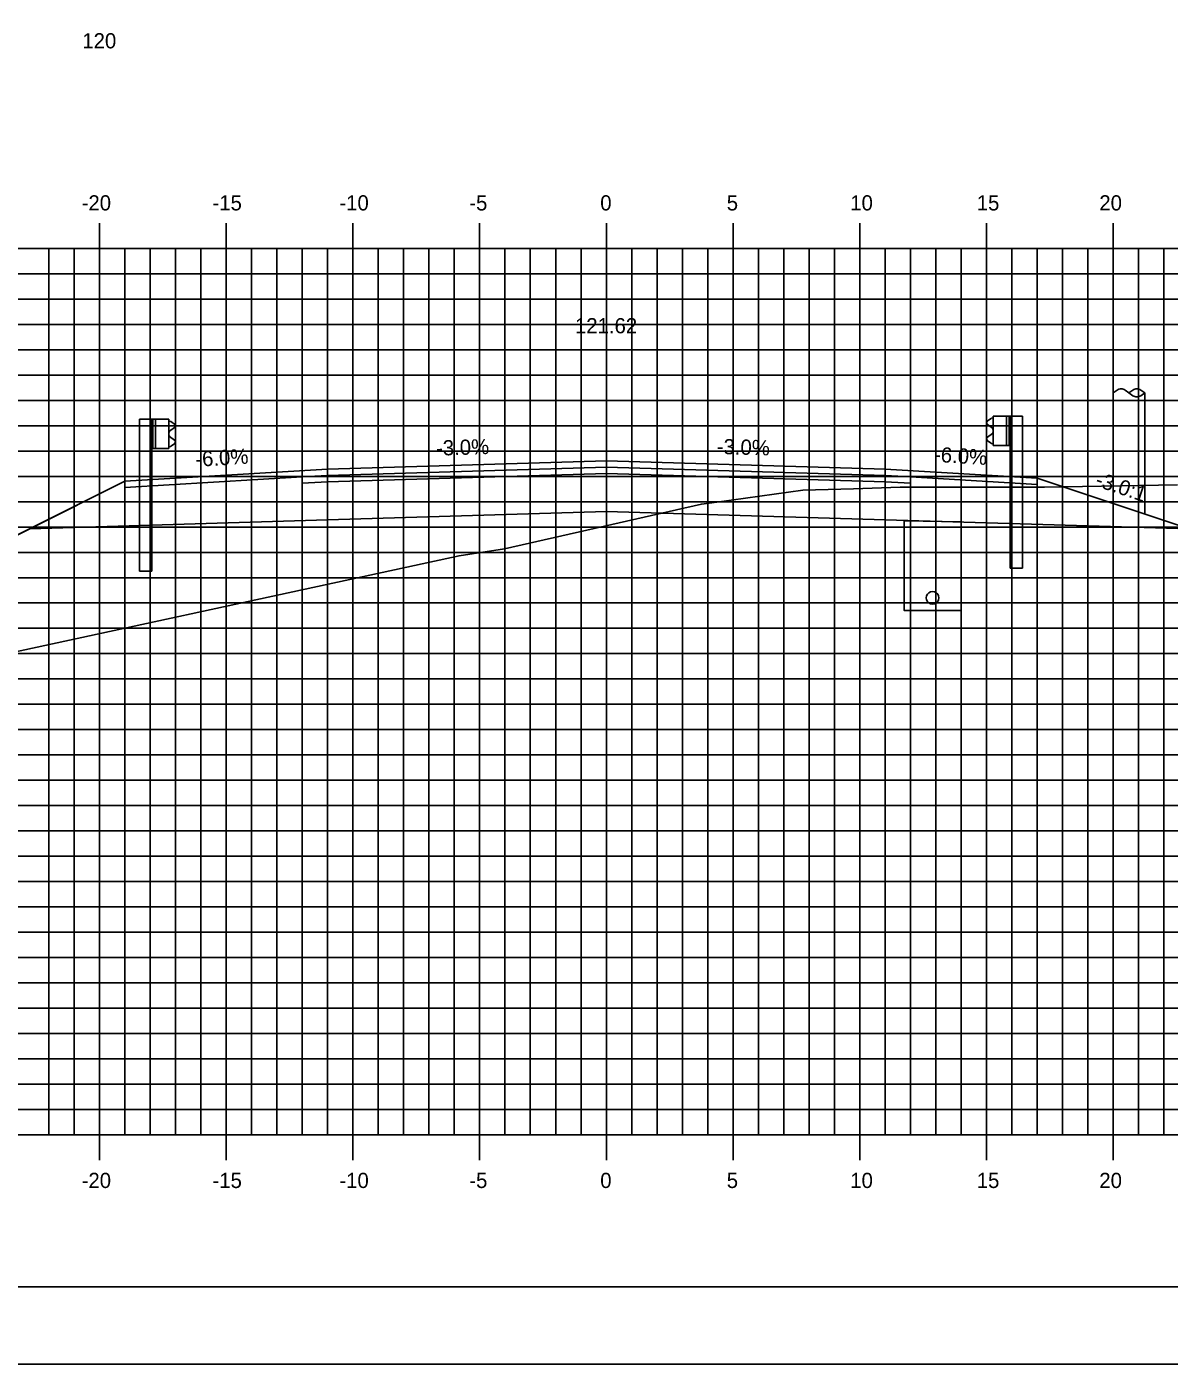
# Model space of a CAD drawing. Extents: x 850598 to 870284, y 366541 to 366651.
# Drawn here: x 858389.5 to 858434.6, y 366541.2 to 366594 of the extents above; entities that cross this region are included whole.
import ezdxf

# ---------------------------------------------------------------- set-up
doc = ezdxf.new("R2010")
doc.units = 0
for name, color, linetype in [('ANNOTATION', 7, 'Continuous'), ('BORDER', 7, 'Continuous'), ('D_Drainage_Underdrain', 7, 'Continuous'), ('D_Drainage_Underdrain_06in', 7, 'Continuous'), ('D_Guardrail_Beam_Lt', 7, 'Continuous'), ('D_Guardrail_Beam_Rt', 7, 'Continuous'), ('D_Roadway_Centerline', 7, 'Continuous'), ('D_Roadway_Centerline_Text', 7, 'Continuous'), ('D_Roadway_Edge_Shoulder', 7, 'Continuous'), ('D_Roadway_Edge_TW', 7, 'Continuous'), ('D_Roadway_Pavement', 7, 'Continuous'), ('D_Roadway_SlopeLines', 7, 'Continuous'), ('D_Roadway_SubGrade', 7, 'Continuous'), ('D_Utilities_Pole_Joint', 7, 'Continuous'), ('H_V ANNOTATION', 7, 'Continuous'), ('MAJOR', 7, 'Continuous'), ('MINOR', 7, 'Continuous'), ('PLOT BOUNDARY', 7, 'Continuous'), ('S_Roadway_Centerline', 7, 'Continuous')]:
    doc.layers.add(name, color=color, linetype=linetype)

msp = doc.modelspace()

# ---------------------------------------------------------------- linework, layer by layer
at = {"layer": 'BORDER'}
msp.add_line((858367.376, 366544.225), (858527.376, 366544.225), dxfattribs=at)
at = {"layer": 'D_Drainage_Underdrain'}
msp.add_lwpolyline([(858426.376, 366574.43), (858426.376, 366570.93), (858424.126, 366570.93), (858424.126, 366574.475)], close=True, dxfattribs=at)
at = {"layer": 'D_Drainage_Underdrain_06in'}
msp.add_lwpolyline([(858425.251, 366571.68), (858425.174, 366571.668), (858425.104, 366571.632), (858425.049, 366571.577), (858425.013, 366571.507), (858425.001, 366571.43), (858425.013, 366571.353), (858425.049, 366571.283), (858425.104, 366571.228), (858425.174, 366571.192), (858425.251, 366571.18), (858425.328, 366571.192), (858425.398, 366571.228), (858425.453, 366571.283), (858425.489, 366571.353), (858425.501, 366571.43), (858425.489, 366571.507), (858425.453, 366571.577), (858425.398, 366571.632), (858425.328, 366571.668)], close=True, dxfattribs=at)
at = {"layer": 'D_Guardrail_Beam_Lt'}
for p, q in [((858393.947, 366578.486), (858393.947, 366572.486)), ((858394.418, 366578.486), (858393.947, 366578.486)), ((858395.105, 366578.486), (858394.418, 366578.486)), ((858394.418, 366578.486), (858394.418, 366577.319)), ((858394.48, 366578.486), (858394.48, 366577.319)), ((858394.584, 366578.486), (858394.584, 366577.319)), ((858395.105, 366577.319), (858395.105, 366578.486)), ((858395.105, 366578.411), (858395.178, 366578.398)), ((858395.195, 366578.392), (858395.339, 366578.292)), ((858395.11, 366577.948), (858395.11, 366577.857)), ((858395.339, 366578.149), (858395.143, 366578.012)), ((858395.143, 366577.793), (858395.339, 366577.656)), ((858394.418, 366577.319), (858395.105, 366577.319)), ((858394.439, 366572.486), (858394.439, 366577.319)), ((858395.178, 366577.406), (858395.105, 366577.394)), ((858395.339, 366577.513), (858395.195, 366577.413)), ((858394.439, 366572.486), (858393.947, 366572.486))]:
    msp.add_line(p, q, dxfattribs=at)
for centre, major_axis, start_param, end_param in [((858395.171, 366578.358), (0.0417, 0), 0.959931, 1.396263), ((858395.288, 366578.22), (0.0877, 0), 5.323254, 7.243116), ((858395.189, 366577.948), (-0.0789, 0), 5.323254, 6.283185), ((858395.189, 366577.857), (-0.0789, 0), 6.283185, 7.243116), ((858395.288, 366577.585), (0.0877, 0), 5.323254, 7.243116), ((858395.171, 366577.447), (0.0417, 0), 4.886922, 5.323254)]:
    msp.add_ellipse(centre, major_axis=major_axis, ratio=0.995501, start_param=start_param, end_param=end_param, dxfattribs=at)
at = {"layer": 'D_Guardrail_Beam_Rt'}
for p, q in [((858427.557, 366578.512), (858427.413, 366578.412)), ((858427.413, 366578.269), (858427.609, 366578.132)), ((858427.647, 366578.531), (858427.574, 366578.518)), ((858427.647, 366578.606), (858428.334, 366578.606)), ((858427.647, 366577.439), (858427.647, 366578.606)), ((858428.168, 366578.606), (858428.168, 366577.439)), ((858428.272, 366578.606), (858428.272, 366577.439)), ((858428.334, 366578.606), (858428.805, 366578.606)), ((858428.334, 366578.606), (858428.334, 366577.439)), ((858428.805, 366578.606), (858428.805, 366572.606)), ((858427.609, 366577.913), (858427.413, 366577.776)), ((858427.642, 366578.068), (858427.642, 366577.977)), ((858427.413, 366577.633), (858427.557, 366577.533)), ((858427.574, 366577.526), (858427.647, 366577.514)), ((858428.334, 366577.439), (858427.647, 366577.439)), ((858428.314, 366572.606), (858428.314, 366577.439)), ((858428.314, 366572.606), (858428.805, 366572.606))]:
    msp.add_line(p, q, dxfattribs=at)
for centre, major_axis, start_param, end_param in [((858427.464, 366578.34), (-0.0877, 0), 5.323254, 7.243116), ((858427.581, 366578.478), (-0.0417, 0), 4.886922, 5.323254), ((858427.464, 366577.705), (-0.0877, 0), 5.323254, 7.243116), ((858427.564, 366578.068), (0.0789, 0), 0, 0.959931), ((858427.564, 366577.977), (0.0789, 0), 5.323254, 6.283185), ((858427.581, 366577.567), (-0.0417, 0), 0.959931, 1.396263)]:
    msp.add_ellipse(centre, major_axis=major_axis, ratio=0.995501, start_param=start_param, end_param=end_param, dxfattribs=at)
at = {"layer": 'D_Roadway_Centerline'}
msp.add_lwpolyline([(858372.376, 366565.532), (858383.376, 366571.032), (858389.631, 366574.16), (858393.376, 366576.032), (858395.376, 366576.152), (858401.376, 366576.512), (858412.376, 366576.842), (858423.376, 366576.512), (858427.376, 366576.272), (858429.376, 366576.152), (858435.376, 366574.152), (858495.021, 366563.225), (858512.376, 366560.046)], dxfattribs=at)
at = {"layer": 'D_Roadway_Edge_Shoulder'}
for points in [[(858401.376, 366576.512), (858395.376, 366576.152), (858395.376, 366576.152), (858393.376, 366576.032), (858393.376, 366575.782), (858400.376, 366576.202), (858401.376, 366576.262)], [(858423.376, 366576.512), (858427.376, 366576.272), (858427.376, 366576.272), (858429.376, 366576.152), (858429.376, 366575.902), (858424.376, 366576.202), (858423.376, 366576.262)]]:
    msp.add_lwpolyline(points, close=True, dxfattribs=at)
at = {"layer": 'D_Roadway_Edge_TW'}
msp.add_lwpolyline([(858401.376, 366576.262), (858401.376, 366576.512), (858412.376, 366576.842), (858423.376, 366576.512), (858423.376, 366576.262), (858412.376, 366576.592)], close=True, dxfattribs=at)
at = {"layer": 'D_Roadway_Pavement'}
for points in [[(858401.376, 366576.012), (858401.376, 366576.262), (858412.376, 366576.592), (858423.376, 366576.262), (858423.376, 366576.012), (858412.376, 366576.342)], [(858401.376, 366576.262), (858400.376, 366576.202), (858400.376, 366575.952), (858401.376, 366576.012)], [(858423.376, 366576.262), (858424.376, 366576.202), (858424.376, 366575.952), (858423.376, 366576.012)]]:
    msp.add_lwpolyline(points, close=True, dxfattribs=at)
at = {"layer": 'D_Roadway_SlopeLines'}
msp.add_lwpolyline([(858393.376, 366576.032), (858383.376, 366571.032)], dxfattribs=at)
at = {"layer": 'D_Roadway_SubGrade'}
for points in [[(858401.376, 366576.012), (858400.376, 366575.952), (858400.376, 366576.202), (858393.376, 366575.782), (858393.376, 366576.032), (858389.631, 366574.16), (858401.376, 366574.512)], [(858401.376, 366574.512), (858401.376, 366576.012), (858412.376, 366576.342), (858423.376, 366576.012), (858423.376, 366574.512), (858412.376, 366574.842)], [(858423.376, 366576.012), (858424.376, 366575.952), (858424.376, 366576.202), (858429.376, 366575.902), (858429.376, 366576.152), (858435.376, 366574.152), (858423.376, 366574.512)]]:
    msp.add_lwpolyline(points, close=True, dxfattribs=at)
msp.add_lwpolyline([(858393.376, 366576.032), (858389.631, 366574.16), (858393.376, 366576.032)], dxfattribs=at)
at = {"layer": 'D_Utilities_Pole_Joint'}
for p, q in [((858432.376, 366579.522), (858432.532, 366579.632)), ((858432.376, 366574.764), (858432.376, 366579.522)), ((858432.845, 366579.632), (858433.001, 366579.522)), ((858433.157, 366579.632), (858433.001, 366579.522)), ((858433.001, 366579.522), (858433.157, 366579.411)), ((858433.626, 366579.522), (858433.47, 366579.632)), ((858433.47, 366579.411), (858433.626, 366579.522)), ((858433.626, 366574.764), (858433.626, 366579.522))]:
    msp.add_line(p, q, dxfattribs=at)
for centre, start, end in [((858432.688, 366579.412), 90, 125.2644), ((858432.688, 366579.412), 54.7356, 90), ((858433.313, 366579.412), 90, 125.2644), ((858433.313, 366579.633), 234.7356, 270), ((858433.313, 366579.412), 54.7356, 90), ((858433.313, 366579.633), 270, 305.2644)]:
    msp.add_arc(centre, 0.271, start, end, dxfattribs=at)
at = {"layer": 'MAJOR'}
for p, q in [((858392.376, 366586.227), (858392.376, 366585.225)), ((858392.376, 366586.227), (858392.376, 366585.225)), ((858397.376, 366586.227), (858397.376, 366585.225)), ((858397.376, 366586.227), (858397.376, 366585.225)), ((858402.376, 366586.227), (858402.376, 366585.225)), ((858402.376, 366586.227), (858402.376, 366585.225)), ((858407.376, 366586.227), (858407.376, 366585.225)), ((858407.376, 366586.227), (858407.376, 366585.225)), ((858412.376, 366586.227), (858412.376, 366585.225)), ((858412.376, 366586.227), (858412.376, 366585.225)), ((858417.376, 366586.227), (858417.376, 366585.225)), ((858417.376, 366586.227), (858417.376, 366585.225)), ((858422.376, 366586.227), (858422.376, 366585.225)), ((858422.376, 366586.227), (858422.376, 366585.225)), ((858427.376, 366586.227), (858427.376, 366585.225)), ((858427.376, 366586.227), (858427.376, 366585.225)), ((858432.376, 366586.227), (858432.376, 366585.225)), ((858432.376, 366586.227), (858432.376, 366585.225)), ((858372.376, 366585.225), (858512.376, 366585.225)), ((858372.376, 366585.225), (858512.376, 366585.225)), ((858372.376, 366585.225), (858512.376, 366585.225)), ((858372.376, 366585.225), (858512.376, 366585.225)), ((858392.376, 366550.225), (858392.376, 366585.225)), ((858392.376, 366550.225), (858392.376, 366585.225)), ((858397.376, 366550.225), (858397.376, 366585.225)), ((858397.376, 366550.225), (858397.376, 366585.225)), ((858402.376, 366550.225), (858402.376, 366585.225)), ((858402.376, 366550.225), (858402.376, 366585.225)), ((858407.376, 366550.225), (858407.376, 366585.225)), ((858407.376, 366550.225), (858407.376, 366585.225)), ((858412.376, 366550.225), (858412.376, 366585.225)), ((858412.376, 366550.225), (858412.376, 366585.225)), ((858417.376, 366550.225), (858417.376, 366585.225)), ((858417.376, 366550.225), (858417.376, 366585.225)), ((858422.376, 366550.225), (858422.376, 366585.225)), ((858422.376, 366550.225), (858422.376, 366585.225)), ((858427.376, 366550.225), (858427.376, 366585.225)), ((858427.376, 366550.225), (858427.376, 366585.225)), ((858432.376, 366550.225), (858432.376, 366585.225)), ((858432.376, 366550.225), (858432.376, 366585.225)), ((858372.376, 366580.225), (858512.376, 366580.225)), ((858372.376, 366580.225), (858512.376, 366580.225)), ((858372.376, 366575.225), (858512.376, 366575.225)), ((858372.376, 366575.225), (858512.376, 366575.225)), ((858372.376, 366570.225), (858512.376, 366570.225)), ((858372.376, 366570.225), (858512.376, 366570.225)), ((858372.376, 366565.225), (858512.376, 366565.225)), ((858372.376, 366565.225), (858512.376, 366565.225)), ((858372.376, 366560.225), (858512.376, 366560.225)), ((858372.376, 366560.225), (858512.376, 366560.225)), ((858372.376, 366555.225), (858512.376, 366555.225)), ((858372.376, 366555.225), (858512.376, 366555.225)), ((858372.376, 366550.225), (858512.376, 366550.225)), ((858372.376, 366550.225), (858512.376, 366550.225)), ((858372.376, 366550.225), (858512.376, 366550.225)), ((858372.376, 366550.225), (858512.376, 366550.225)), ((858392.376, 366549.223), (858392.376, 366550.225)), ((858392.376, 366549.223), (858392.376, 366550.225)), ((858397.376, 366549.223), (858397.376, 366550.225)), ((858397.376, 366549.223), (858397.376, 366550.225)), ((858402.376, 366549.223), (858402.376, 366550.225)), ((858402.376, 366549.223), (858402.376, 366550.225)), ((858407.376, 366549.223), (858407.376, 366550.225)), ((858407.376, 366549.223), (858407.376, 366550.225)), ((858412.376, 366549.223), (858412.376, 366550.225)), ((858412.376, 366549.223), (858412.376, 366550.225)), ((858417.376, 366549.223), (858417.376, 366550.225)), ((858417.376, 366549.223), (858417.376, 366550.225)), ((858422.376, 366549.223), (858422.376, 366550.225)), ((858422.376, 366549.223), (858422.376, 366550.225)), ((858427.376, 366549.223), (858427.376, 366550.225)), ((858427.376, 366549.223), (858427.376, 366550.225)), ((858432.376, 366549.223), (858432.376, 366550.225)), ((858432.376, 366549.223), (858432.376, 366550.225))]:
    msp.add_line(p, q, dxfattribs=at)
at = {"layer": 'MINOR'}
for p, q in [((858390.376, 366550.225), (858390.376, 366585.225)), ((858390.376, 366550.225), (858390.376, 366585.225)), ((858391.376, 366550.225), (858391.376, 366585.225)), ((858391.376, 366550.225), (858391.376, 366585.225)), ((858393.376, 366550.225), (858393.376, 366585.225)), ((858393.376, 366550.225), (858393.376, 366585.225)), ((858394.376, 366550.225), (858394.376, 366585.225)), ((858394.376, 366550.225), (858394.376, 366585.225)), ((858395.376, 366550.225), (858395.376, 366585.225)), ((858395.376, 366550.225), (858395.376, 366585.225)), ((858396.376, 366550.225), (858396.376, 366585.225)), ((858396.376, 366550.225), (858396.376, 366585.225)), ((858398.376, 366550.225), (858398.376, 366585.225)), ((858398.376, 366550.225), (858398.376, 366585.225)), ((858399.376, 366550.225), (858399.376, 366585.225)), ((858399.376, 366550.225), (858399.376, 366585.225)), ((858400.376, 366550.225), (858400.376, 366585.225)), ((858400.376, 366550.225), (858400.376, 366585.225)), ((858401.376, 366550.225), (858401.376, 366585.225)), ((858401.376, 366550.225), (858401.376, 366585.225)), ((858403.376, 366550.225), (858403.376, 366585.225)), ((858403.376, 366550.225), (858403.376, 366585.225)), ((858404.376, 366550.225), (858404.376, 366585.225)), ((858404.376, 366550.225), (858404.376, 366585.225)), ((858405.376, 366550.225), (858405.376, 366585.225)), ((858405.376, 366550.225), (858405.376, 366585.225)), ((858406.376, 366550.225), (858406.376, 366585.225)), ((858406.376, 366550.225), (858406.376, 366585.225)), ((858408.376, 366550.225), (858408.376, 366585.225)), ((858408.376, 366550.225), (858408.376, 366585.225)), ((858409.376, 366550.225), (858409.376, 366585.225)), ((858409.376, 366550.225), (858409.376, 366585.225)), ((858410.376, 366550.225), (858410.376, 366585.225)), ((858410.376, 366550.225), (858410.376, 366585.225)), ((858411.376, 366550.225), (858411.376, 366585.225)), ((858411.376, 366550.225), (858411.376, 366585.225)), ((858413.376, 366550.225), (858413.376, 366585.225)), ((858413.376, 366550.225), (858413.376, 366585.225)), ((858414.376, 366550.225), (858414.376, 366585.225)), ((858414.376, 366550.225), (858414.376, 366585.225)), ((858415.376, 366550.225), (858415.376, 366585.225)), ((858415.376, 366550.225), (858415.376, 366585.225)), ((858416.376, 366550.225), (858416.376, 366585.225)), ((858416.376, 366550.225), (858416.376, 366585.225)), ((858418.376, 366550.225), (858418.376, 366585.225)), ((858418.376, 366550.225), (858418.376, 366585.225)), ((858419.376, 366550.225), (858419.376, 366585.225)), ((858419.376, 366550.225), (858419.376, 366585.225)), ((858420.376, 366550.225), (858420.376, 366585.225)), ((858420.376, 366550.225), (858420.376, 366585.225)), ((858421.376, 366550.225), (858421.376, 366585.225)), ((858421.376, 366550.225), (858421.376, 366585.225)), ((858423.376, 366550.225), (858423.376, 366585.225)), ((858423.376, 366550.225), (858423.376, 366585.225)), ((858424.376, 366550.225), (858424.376, 366585.225)), ((858424.376, 366550.225), (858424.376, 366585.225)), ((858425.376, 366550.225), (858425.376, 366585.225)), ((858425.376, 366550.225), (858425.376, 366585.225)), ((858426.376, 366550.225), (858426.376, 366585.225)), ((858426.376, 366550.225), (858426.376, 366585.225)), ((858428.376, 366550.225), (858428.376, 366585.225)), ((858428.376, 366550.225), (858428.376, 366585.225)), ((858429.376, 366550.225), (858429.376, 366585.225)), ((858429.376, 366550.225), (858429.376, 366585.225)), ((858430.376, 366550.225), (858430.376, 366585.225)), ((858430.376, 366550.225), (858430.376, 366585.225)), ((858431.376, 366550.225), (858431.376, 366585.225)), ((858431.376, 366550.225), (858431.376, 366585.225)), ((858433.376, 366550.225), (858433.376, 366585.225)), ((858433.376, 366550.225), (858433.376, 366585.225)), ((858434.376, 366550.225), (858434.376, 366585.225)), ((858434.376, 366550.225), (858434.376, 366585.225)), ((858372.376, 366584.225), (858512.376, 366584.225)), ((858372.376, 366584.225), (858512.376, 366584.225)), ((858372.376, 366583.225), (858512.376, 366583.225)), ((858372.376, 366583.225), (858512.376, 366583.225)), ((858372.376, 366582.225), (858512.376, 366582.225)), ((858372.376, 366582.225), (858512.376, 366582.225)), ((858372.376, 366581.225), (858512.376, 366581.225)), ((858372.376, 366581.225), (858512.376, 366581.225)), ((858372.376, 366579.225), (858512.376, 366579.225)), ((858372.376, 366579.225), (858512.376, 366579.225)), ((858372.376, 366578.225), (858512.376, 366578.225)), ((858372.376, 366578.225), (858512.376, 366578.225)), ((858372.376, 366577.225), (858512.376, 366577.225)), ((858372.376, 366577.225), (858512.376, 366577.225)), ((858372.376, 366576.225), (858512.376, 366576.225)), ((858372.376, 366576.225), (858512.376, 366576.225)), ((858372.376, 366574.225), (858512.376, 366574.225)), ((858372.376, 366574.225), (858512.376, 366574.225)), ((858372.376, 366573.225), (858512.376, 366573.225)), ((858372.376, 366573.225), (858512.376, 366573.225)), ((858372.376, 366572.225), (858512.376, 366572.225)), ((858372.376, 366572.225), (858512.376, 366572.225)), ((858372.376, 366571.225), (858512.376, 366571.225)), ((858372.376, 366571.225), (858512.376, 366571.225)), ((858372.376, 366569.225), (858512.376, 366569.225)), ((858372.376, 366569.225), (858512.376, 366569.225)), ((858372.376, 366568.225), (858512.376, 366568.225)), ((858372.376, 366568.225), (858512.376, 366568.225)), ((858372.376, 366567.225), (858512.376, 366567.225)), ((858372.376, 366567.225), (858512.376, 366567.225)), ((858372.376, 366566.225), (858512.376, 366566.225)), ((858372.376, 366566.225), (858512.376, 366566.225)), ((858372.376, 366564.225), (858512.376, 366564.225)), ((858372.376, 366564.225), (858512.376, 366564.225)), ((858372.376, 366563.225), (858512.376, 366563.225)), ((858372.376, 366563.225), (858512.376, 366563.225)), ((858372.376, 366562.225), (858512.376, 366562.225)), ((858372.376, 366562.225), (858512.376, 366562.225)), ((858372.376, 366561.225), (858512.376, 366561.225)), ((858372.376, 366561.225), (858512.376, 366561.225)), ((858372.376, 366559.225), (858512.376, 366559.225)), ((858372.376, 366559.225), (858512.376, 366559.225)), ((858372.376, 366558.225), (858512.376, 366558.225)), ((858372.376, 366558.225), (858512.376, 366558.225)), ((858372.376, 366557.225), (858512.376, 366557.225)), ((858372.376, 366557.225), (858512.376, 366557.225)), ((858372.376, 366556.225), (858512.376, 366556.225)), ((858372.376, 366556.225), (858512.376, 366556.225)), ((858372.376, 366554.225), (858512.376, 366554.225)), ((858372.376, 366554.225), (858512.376, 366554.225)), ((858372.376, 366553.225), (858512.376, 366553.225)), ((858372.376, 366553.225), (858512.376, 366553.225)), ((858372.376, 366552.225), (858512.376, 366552.225)), ((858372.376, 366552.225), (858512.376, 366552.225)), ((858372.376, 366551.225), (858512.376, 366551.225)), ((858372.376, 366551.225), (858512.376, 366551.225))]:
    msp.add_line(p, q, dxfattribs=at)
at = {"layer": 'PLOT BOUNDARY'}
msp.add_lwpolyline([(858359.283, 366541.166), (858529.283, 366541.166), (858529.283, 366651.166), (858359.283, 366651.166)], close=True, dxfattribs=at)
at = {"layer": 'S_Roadway_Centerline'}
msp.add_lwpolyline([(858372.376, 366562.819), (858378.306, 366566.081), (858381.367, 366567.76), (858384.91, 366568.401), (858406.567, 366573.092), (858408.353, 366573.362), (858416.127, 366575.129), (858416.73, 366575.21), (858420.127, 366575.686), (858422.126, 366575.739), (858423.966, 366575.804), (858429.662, 366575.799), (858434.913, 366575.888)], dxfattribs=at)

# ---------------------------------------------------------------- texts
at = {"layer": 'ANNOTATION'}
for s, rotation, p in [('-3.0%', 1.7184, (858405.664, 366577.042)), ('-3.0%', 358.2816, (858416.724, 366577.112)), ('-6.0%', 3.4336, (858396.173, 366576.602)), ('-6.0%', 356.5664, (858425.293, 366576.799)), ('-3.0:1', 341.5651, (858431.63, 366575.855))]:
    msp.add_text(s, height=0.6, rotation=rotation, dxfattribs=at).set_placement(p)
at = {"layer": 'D_Roadway_Centerline'}
for s, p in [('C', (858412.371, 366576.842)), ('C', (858412.371, 366576.842)), ('L', (858412.376, 366576.835)), ('L', (858412.376, 366576.835))]:
    msp.add_text(s, height=0.0146, dxfattribs=at).set_placement(p)
at = {"layer": 'D_Roadway_Centerline_Text'}
msp.add_text('121.62', height=0.6, dxfattribs=at).set_placement((858411.137, 366581.874))
at = {"layer": 'H_V ANNOTATION'}
for s, p in [('120', (858391.696, 366593.125)), ('-20', (858391.67, 366586.725)), ('-15', (858396.833, 366586.725)), ('-10', (858401.841, 366586.725)), ('-5', (858406.967, 366586.725)), ('0', (858412.135, 366586.725)), ('5', (858417.127, 366586.725)), ('10', (858422.001, 366586.725)), ('15', (858426.993, 366586.725)), ('20', (858431.83, 366586.725)), ('-20', (858391.67, 366548.125)), ('-15', (858396.833, 366548.125)), ('-10', (858401.841, 366548.125)), ('-5', (858406.967, 366548.125)), ('0', (858412.135, 366548.125)), ('5', (858417.127, 366548.125)), ('10', (858422.001, 366548.125)), ('15', (858426.993, 366548.125)), ('20', (858431.83, 366548.125))]:
    msp.add_text(s, height=0.6, dxfattribs=at).set_placement(p)

doc.saveas('drawing.dxf')
